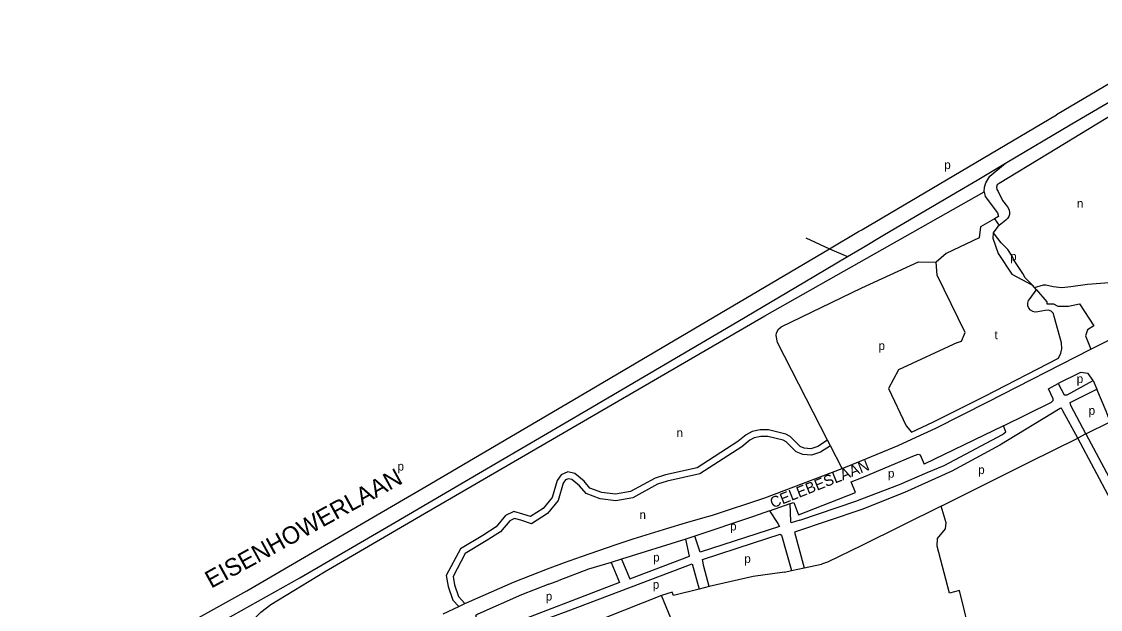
# Model space of a CAD drawing. Extents: x 162883 to 165538, y 383986 to 385172.
# Drawn here: x 162964.2 to 163459.6, y 384308.7 to 384578.7 of the extents above; entities that cross this region are included whole.
import ezdxf

# ---------------------------------------------------------------- set-up
doc = ezdxf.new("R2010")
doc.units = 0
for name, color, linetype in [('BLT_Basislijn', 7, 'Continuous'), ('BLT_Centroide', 7, 'Continuous'), ('BLT_Straatnaam', 7, 'Continuous'), ('BLT_Straatnaam_hoofdweg', 7, 'Continuous'), ('BLT_Vlakafsluiter', 7, 'Continuous')]:
    doc.layers.add(name, color=color, linetype=linetype)

msp = doc.modelspace()

# ---------------------------------------------------------------- linework, layer by layer
at = {"layer": 'BLT_Basislijn'}
for p, q in [((163511.91, 384578.65), (163439.44, 384535.82)), ((163446.47, 384531.63), (163521.25, 384575.69)), ((163378.75, 384500), (163439.44, 384535.82)), ((163393.01, 384500), (163403.01, 384505.89)), ((163350, 384483.1), (163378.75, 384500)), ((163360.49, 384480.83), (163393.01, 384500)), ((163410.97, 384488.06), (163413.04, 384485.08)), ((163335.11, 384474.31), (163348.52, 384482.23)), ((163348.52, 384482.23), (163350, 384483.1)), ((163350, 384474.64), (163360.49, 384480.83)), ((163222.45, 384407.82), (163335.11, 384474.31)), ((163343.41, 384470.74), (163350, 384474.64)), ((163429.33, 384456.48), (163428.39, 384457.56)), ((163430.27, 384455.4), (163429.33, 384456.48)), ((163456.29, 384413.81), (163457.88, 384409.93)), ((163149.87, 384365.23), (163222.45, 384407.82)), ((163415.1, 384393.07), (163378.6, 384375.41)), ((163452.9, 384389.28), (163464.08, 384394.8)), ((163452.9, 384389.28), (163449.15, 384387.42)), ((163340.93, 384373.36), (163335.6, 384383.8)), ((163427.17, 384376.47), (163449.15, 384387.42)), ((163340.93, 384373.36), (163350, 384377.08)), ((163386.45, 384356.18), (163427.17, 384376.47)), ((163097.69, 384334.8), (163149.87, 384365.23)), ((163320.88, 384352.17), (163347.15, 384362.46)), ((163321.6, 384349.67), (163347.33, 384358.46)), ((163347.33, 384358.46), (163350, 384359.47)), ((163307.59, 384354.07), (163317.05, 384357.41)), ((163386.45, 384356.18), (163350, 384338.15)), ((163269.23, 384340.99), (163239.68, 384331.83)), ((163273.4, 384342.38), (163269.23, 384340.99)), ((163234.88, 384330.34), (163238.68, 384321.09)), ((163239.68, 384331.83), (163243.42, 384322.7)), ((163323.47, 384327.82), (163331.54, 384329.57)), ((162986.87, 384264.62), (163091.98, 384323.19)), ((163314.5, 384325.87), (163317.7, 384326.58)), ((163317.7, 384326.58), (163323.47, 384327.82)), ((163206.3, 384320.29), (163210.92, 384322.07)), ((163279.94, 384319.28), (163275.27, 384318.06)), ((163157.73, 384306.76), (163164.89, 384310.08))]:
    msp.add_line(p, q, dxfattribs=at)
for points in [[(163521.33, 384567.5), (163498.49, 384555.31), (163469.31, 384538.43), (163435.36, 384517.78), (163413.06, 384504.27), (163412.24, 384503.63), (163411.82, 384502.61), (163411.97, 384501.48), (163412.58, 384500.68), (163414.59, 384496.48), (163416.99, 384493.52), (163417.6, 384492.48), (163417.88, 384491.39), (163417.83, 384490.09), (163417.51, 384489.12), (163416.95, 384488.25), (163416.21, 384487.54), (163413.04, 384485.08)], [(163416.03, 384513.61), (163446.47, 384531.63)], [(163403.01, 384505.89), (163416.03, 384513.61)], [(163406.25, 384500.5), (163406.42, 384502.56), (163406.99, 384504.54), (163408.86, 384507.6), (163416.03, 384513.61)], [(163014.85, 384262.6), (163010.31, 384266.1), (163010.26, 384272.54), (163015.98, 384275.99), (163044.78, 384289.14), (163054.55, 384290.51), (163057.11, 384293.33), (163061.01, 384294.75), (163074.05, 384307.52), (163078.61, 384311.03), (163103.23, 384326.02), (163147.41, 384351.74), (163305.54, 384443.59), (163406.25, 384500.5)], [(163406.25, 384500.5), (163406.64, 384498.37), (163412.34, 384490.79), (163412.83, 384489.1), (163410.97, 384488.06)], [(163410.97, 384488.06), (163404.53, 384484.47), (163403.9, 384479.35), (163388.76, 384472.23), (163384.23, 384468.23)], [(163413.04, 384485.08), (163412.44, 384484.61), (163410.39, 384481.61)], [(163410.39, 384481.61), (163410.21, 384479.22), (163412.71, 384472.23), (163418.98, 384462.74), (163428.39, 384457.56)], [(163428.39, 384457.56), (163425, 384461), (163424, 384463), (163420, 384469), (163419, 384471), (163417, 384474), (163414, 384477), (163411, 384481), (163410.39, 384481.61)], [(163223.7, 384400.24), (163293.03, 384440.93), (163323.85, 384459.13), (163343.41, 384470.74)], [(163350, 384456.44), (163376.04, 384468.26), (163384.23, 384468.23)], [(163393.94, 384431.26), (163395.87, 384431.97), (163397.44, 384435.81), (163384.68, 384462.21), (163384.23, 384468.23)], [(163429.33, 384456.48), (163433.39, 384457.8), (163434.52, 384457.8), (163437.94, 384457.05), (163441.94, 384456.6), (163445.95, 384456.94), (163453.6, 384458.03), (163465.61, 384459.06), (163476.84, 384460.86), (163485.52, 384462.96), (163494.06, 384466.21)], [(163455.14, 384428.3), (163505.69, 384453.68), (163527.26, 384463.5)], [(163334.23, 384386.49), (163311.36, 384431.35), (163310.72, 384434.54), (163310.88, 384435.66), (163311.74, 384437.34), (163313.01, 384438.51), (163350, 384456.44)], [(163406.49, 384406.7), (163440.27, 384424.04), (163441.37, 384426.38), (163441.81, 384428.42), (163441.75, 384431.2), (163440.97, 384433.82), (163438.36, 384443.2), (163437.99, 384444.6), (163436.99, 384445.7), (163435.75, 384446.2), (163434.16, 384446.06), (163430.84, 384445.34), (163429.58, 384445.25), (163428.48, 384445.53), (163427.44, 384446.2), (163426.71, 384447.11), (163426.31, 384448.15), (163426.25, 384449.39), (163426.59, 384450.56), (163427.31, 384451.57), (163430.1, 384455.34), (163430.27, 384455.4)], [(163430.27, 384455.4), (163435, 384450), (163435, 384449), (163438, 384449), (163440, 384448), (163445, 384448), (163450, 384449), (163456.63, 384438.91), (163453.61, 384437.16), (163452.69, 384434.42), (163455.14, 384428.3)], [(163393.94, 384431.26), (163366.88, 384418.67), (163362.32, 384410.12), (163370.34, 384393.04), (163372.91, 384390.13), (163382.63, 384394.69), (163406.49, 384406.7)], [(163407.85, 384404.03), (163455.14, 384428.3)], [(163456.29, 384413.81), (163453.93, 384417.06), (163450.46, 384417.47), (163440.18, 384412.4)], [(163415.1, 384393.07), (163437.08, 384403.96), (163437.92, 384404.72), (163437.92, 384405.36), (163435.7, 384410.04), (163440.18, 384412.4)], [(163440.18, 384412.4), (163442.98, 384407.32), (163444.35, 384407.33), (163456.29, 384413.81)], [(163452.9, 384389.28), (163446.03, 384402.4), (163445.69, 384403.67), (163457.88, 384409.93)], [(163464.08, 384394.8), (163462.26, 384399.83), (163457.88, 384409.93)], [(163375.02, 384387.81), (163383.94, 384391.99), (163407.85, 384404.03)], [(163091.98, 384323.19), (163135.53, 384348.64), (163174.05, 384371.12), (163223.7, 384400.24)], [(163449.15, 384387.42), (163442.35, 384399.97), (163441.65, 384401.08), (163441.11, 384400.92), (163413.39, 384384.2), (163391.36, 384372.19), (163369.6, 384362.47), (163350, 384354.64)], [(163380.02, 384371.6), (163387.85, 384374.77), (163414.62, 384389.1), (163416.1, 384390.25), (163415.1, 384393.07)], [(163452.9, 384389.28), (163463.6, 384369.3), (163464.55, 384369.39), (163470.28, 384371.63), (163470.76, 384372.11), (163466.16, 384389.07), (163464.08, 384394.8)], [(163334.23, 384386.49), (163329.77, 384383.61), (163326.56, 384382.52), (163323.6, 384382.74), (163321.64, 384383.6), (163317.11, 384388.06), (163315.11, 384389.27), (163307.24, 384391.13), (163303.31, 384391.13), (163299.63, 384390.35), (163296.89, 384388.96), (163293.11, 384385.87), (163274.41, 384373.79), (163259.91, 384370.5), (163255.08, 384369.01), (163243.81, 384362.9), (163236.97, 384361.58), (163230.63, 384362.42), (163225.18, 384364.42), (163222.5, 384367.69), (163218.17, 384371.2), (163215.01, 384371.88), (163211.88, 384370.6), (163210.1, 384367.93), (163207.86, 384360.12), (163203.66, 384355.09), (163197.94, 384351.37), (163194.34, 384352.51), (163190.21, 384353.65), (163186.46, 384351.78), (163182.04, 384346.65), (163175.99, 384342.74), (163165.67, 384336.52), (163159.17, 384324.32), (163160.01, 384319.25), (163162.16, 384313.03), (163164.89, 384310.08)], [(163335.6, 384383.8), (163331.09, 384380.89), (163326.95, 384379.49), (163322.86, 384379.79), (163319.93, 384381.08), (163315.26, 384385.68), (163313.96, 384386.45), (163306.89, 384388.13), (163303.62, 384388.13), (163300.64, 384387.5), (163298.54, 384386.43), (163294.88, 384383.44), (163275.6, 384370.98), (163260.69, 384367.6), (163256.25, 384366.23), (163244.83, 384360.04), (163237.06, 384358.54), (163229.9, 384359.48), (163223.38, 384361.88), (163220.38, 384365.55), (163216.84, 384368.41), (163215.29, 384368.75), (163213.87, 384368.17), (163212.85, 384366.65), (163210.56, 384358.68), (163205.67, 384352.82), (163198.39, 384348.08), (163193.49, 384349.64), (163190.53, 384350.45), (163188.34, 384349.36), (163184.03, 384344.37), (163177.58, 384340.19), (163167.93, 384334.38), (163162.3, 384323.81), (163162.93, 384319.99), (163164.79, 384314.61), (163167.76, 384311.41)], [(163350, 384377.08), (163366.78, 384383.95), (163375.02, 384387.81)], [(163335.6, 384383.8), (163334.23, 384386.49)], [(163467.23, 384359.66), (163464.17, 384359.13), (163449.15, 384387.42)], [(163349.89, 384369.22), (163373.47, 384379.13), (163375.94, 384380.03), (163376.74, 384379.74), (163378.6, 384375.41)], [(163281.49, 384352.01), (163305.44, 384359.97), (163340.93, 384373.36)], [(163347.15, 384362.46), (163345.15, 384367.34), (163349.89, 384369.22)], [(163350, 384359.47), (163367.35, 384366.04), (163380.02, 384371.6)], [(163317.05, 384357.41), (163318.75, 384357.88), (163320.61, 384352.89), (163320.88, 384352.17)], [(163307.59, 384354.07), (163300.28, 384351.45), (163273.4, 384342.38)], [(163307.59, 384354.07), (163311.4, 384348.18), (163312.28, 384346.8), (163275.77, 384334.97), (163275.14, 384336.92), (163273.4, 384342.38)], [(163321.6, 384349.67), (163317.52, 384348.49), (163317.49, 384349.1), (163317.05, 384357.41)], [(163350, 384354.64), (163319.18, 384344.2), (163323.47, 384327.82)], [(163406.15, 384271.34), (163394.86, 384317.36), (163390.31, 384316.24), (163384.56, 384337.76), (163384.7, 384341.27), (163388.47, 384345.75), (163388.79, 384348.49), (163386.45, 384356.18)], [(163190.13, 384321.29), (163197.9, 384324.34), (163205.69, 384327.33), (163213.51, 384330.23), (163221.36, 384333.07), (163229.24, 384335.82), (163237.14, 384338.5), (163245.07, 384341.11), (163253.02, 384343.64), (163260.99, 384346.09), (163268.99, 384348.47), (163277.01, 384350.76), (163281.49, 384352.01)], [(163279.94, 384319.28), (163277.45, 384328.38), (163276.86, 384331.61), (163300.24, 384339.36), (163312.57, 384343.25), (163313.15, 384342.78), (163317.7, 384326.58)], [(163243.42, 384322.7), (163270.96, 384333.22), (163269.23, 384340.99)], [(163350, 384338.15), (163334.32, 384330.4), (163331.54, 384329.57)], [(162964.15, 384260.53), (163022.21, 384292), (163067.54, 384317.25), (163097.69, 384334.8)], [(163181.14, 384284.65), (163177.71, 384294.32), (163215.11, 384308.05), (163272.07, 384329.67), (163275.27, 384318.06)], [(163234.88, 384330.34), (163224.57, 384327.14), (163210.92, 384322.07)], [(163239.68, 384331.83), (163234.88, 384330.34)], [(163314.5, 384325.87), (163300.18, 384323.9), (163279.94, 384319.28)], [(163167.76, 384311.41), (163169.91, 384312.4), (163190.13, 384321.29)], [(163238.68, 384321.09), (163183.81, 384300), (163176.76, 384297.24), (163175.71, 384297.35), (163175.55, 384297.54), (163174.66, 384300), (163172.69, 384305.95)], [(163206.3, 384320.29), (163193.68, 384315.49), (163173.69, 384306.48), (163172.69, 384305.95)], [(163258.04, 384315.15), (163181.14, 384284.65)], [(163187.07, 384235.63), (163275.73, 384271.9), (163258.04, 384315.15)], [(163263.56, 384315.08), (163263, 384316.67), (163258.04, 384315.15)], [(163275.27, 384318.06), (163263.56, 384315.08)], [(163164.89, 384310.08), (163167.76, 384311.41)]]:
    msp.add_lwpolyline(points, dxfattribs=at)
at = {"layer": 'BLT_Vlakafsluiter'}
for p, q in [((163324.35, 384479.33), (163335.11, 384474.31)), ((163335.11, 384474.31), (163343.41, 384470.74))]:
    msp.add_line(p, q, dxfattribs=at)

# ---------------------------------------------------------------- texts
at = {"layer": 'BLT_Centroide'}
for s, p in [('p', (163387.89, 384510.92)), ('n', (163448.8, 384493.15)), ('p', (163418.15, 384468.84)), ('t', (163410.96, 384432.81)), ('p', (163357.67, 384427.84)), ('p', (163448.7, 384412.67)), ('p', (163454.19, 384398.09)), ('n', (163264.92, 384387.87)), ('p', (163136.8, 384372.48)), ('p', (163403.47, 384370.86)), ('p', (163362.03, 384369.22)), ('n', (163247.9, 384350.2)), ('p', (163289.51, 384344.99)), ('p', (163254.18, 384330.7)), ('p', (163296.05, 384330.04)), ('p', (163254.01, 384318.2)), ('p', (163204.88, 384312.8))]:
    msp.add_text(s, height=4, dxfattribs=at).set_placement(p)
at = {"layer": 'BLT_Straatnaam'}
msp.add_text('CELEBESLAAN', height=4.9999, rotation=21.6406, dxfattribs=at).set_placement((163309.07, 384355.12))
at = {"layer": 'BLT_Straatnaam_hoofdweg'}
msp.add_text('EISENHOWERLAAN', height=8, rotation=28.7966, dxfattribs=at).set_placement((163051.22, 384318.21))

doc.saveas('drawing.dxf')
